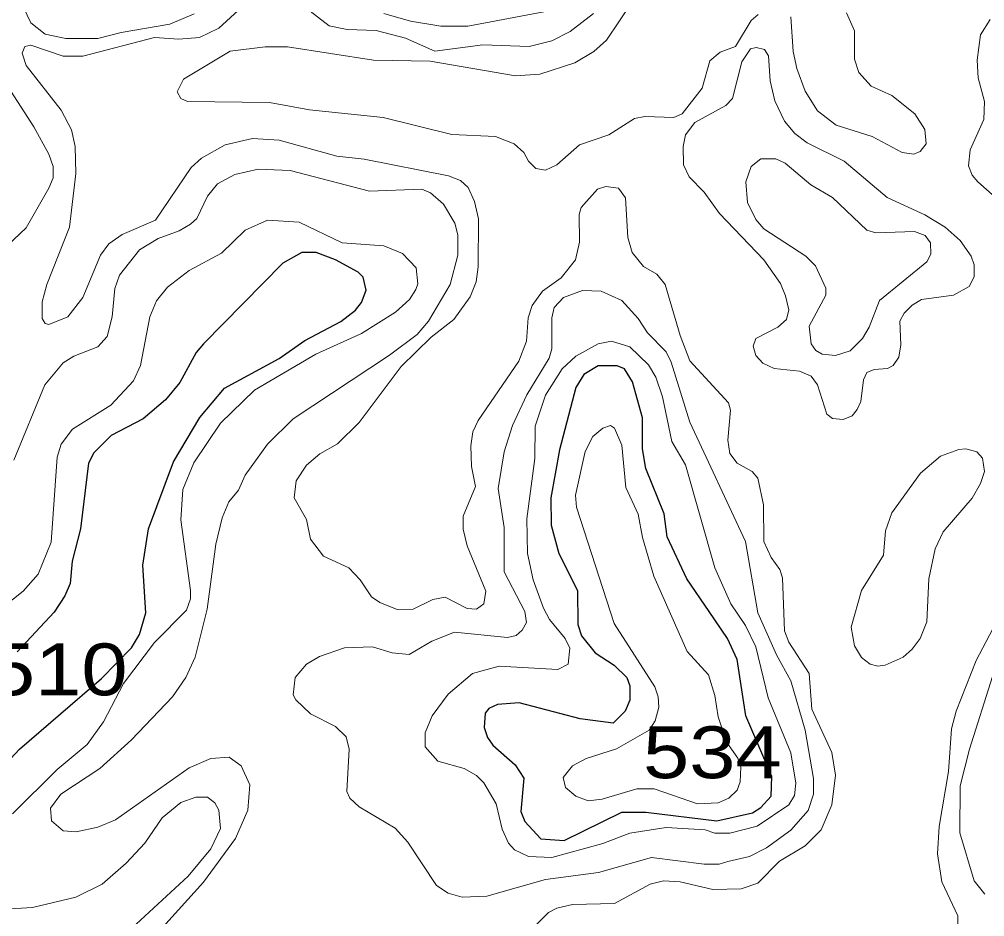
# Model space of a CAD drawing. Extents: x 577 to 602.9, y 7483.8 to 7511.6.
# Drawn here: x 599.599 to 601.089, y 7486.922 to 7488.307 of the extents above; entities that cross this region are included whole.
import ezdxf
from ezdxf.enums import TextEntityAlignment as Align

# ---------------------------------------------------------------- set-up
doc = ezdxf.new("R2010")
doc.units = 0
doc.header["$LTSCALE"] = 0.032
doc.layers.add('1', color=7, linetype='Continuous', lineweight=25)
doc.layers.add('2', color=7, linetype='Continuous', lineweight=13)
doc.layers.add('61', color=7, linetype='Continuous')

msp = doc.modelspace()

# ---------------------------------------------------------------- linework, layer by layer
at = {"layer": '1'}
msp.add_lwpolyline([(599.5786, 7487.1589), (599.5992, 7487.1808), (599.7257, 7487.29), (599.7717, 7487.3374), (599.7844, 7487.3581), (599.794, 7487.3915), (599.7892, 7487.4646), (599.798, 7487.5211), (599.8369, 7487.6244), (599.8775, 7487.6928), (599.9156, 7487.7382), (599.9999, 7487.7835), (600.0397, 7487.8113), (600.0953, 7487.8407), (600.1176, 7487.8582), (600.1272, 7487.8702), (600.1343, 7487.8892), (600.1295, 7487.9091), (600.1216, 7487.9171), (600.0866, 7487.9362), (600.0572, 7487.9473), (600.0349, 7487.9473), (600.0055, 7487.9306), (599.883, 7487.8065), (599.8719, 7487.793), (599.8465, 7487.7469), (599.8242, 7487.7199), (599.79, 7487.6904), (599.7407, 7487.665), (599.7137, 7487.638), (599.7057, 7487.6221), (599.693, 7487.5211), (599.6803, 7487.471), (599.6771, 7487.4368), (599.6691, 7487.4177), (599.6524, 7487.3923), (599.5952, 7487.331)], dxfattribs=at)
msp.add_lwpolyline([(600.6636, 7487.3934), (600.6289, 7487.4439), (600.5987, 7487.5084), (600.5939, 7487.5441), (600.5661, 7487.6141), (600.5605, 7487.6443), (600.5605, 7487.692), (600.5454, 7487.7477), (600.5327, 7487.7676), (600.5216, 7487.7724), (600.4921, 7487.7724), (600.4699, 7487.7588), (600.4579, 7487.739), (600.4325, 7487.6427), (600.419, 7487.5688), (600.4198, 7487.5266), (600.4317, 7487.4829), (600.4603, 7487.4257), (600.4611, 7487.3732), (600.4667, 7487.3557), (600.4874, 7487.3294), (600.5168, 7487.3104), (600.5367, 7487.2913), (600.5414, 7487.2785), (600.5409, 7487.2566), (600.534, 7487.2394), (600.5156, 7487.221), (600.4643, 7487.2277), (600.3705, 7487.2523), (600.3371, 7487.2499), (600.3236, 7487.2436), (600.318, 7487.2364), (600.3164, 7487.2141), (600.3212, 7487.199), (600.3299, 7487.1871), (600.3641, 7487.1569), (600.3776, 7487.1362), (600.3729, 7487.0845), (600.3792, 7487.0694), (600.4039, 7487.0424), (600.4397, 7487.04), (600.5287, 7487.0837), (600.5661, 7487.0837), (600.6753, 7487.0704), (600.7307, 7487.0829), (600.7434, 7487.0909), (600.7593, 7487.1084), (600.7601, 7487.1386), (600.7204, 7487.2324), (600.7068, 7487.3191), (600.6917, 7487.3517)], close=True, dxfattribs=at)
at = {"layer": '2'}
for points in [[(599.5578, 7488.4236), (599.6167, 7488.3019), (599.6389, 7488.2844), (599.6707, 7488.2773), (599.72, 7488.2773), (599.7558, 7488.2868), (599.8313, 7488.2996), (599.8687, 7488.3155)], [(600.5454, 7488.3345), (600.5049, 7488.2749), (600.4858, 7488.2574), (600.4564, 7488.2399), (600.4023, 7488.2224), (600.3649, 7488.22), (600.2329, 7488.2423), (600.1454, 7488.2439), (600.0126, 7488.2646), (599.9785, 7488.2646), (599.9244, 7488.2582), (599.852, 7488.2145), (599.8425, 7488.1954), (599.848, 7488.185), (599.8584, 7488.1803), (599.9848, 7488.1787), (600.0468, 7488.1676), (600.1606, 7488.1556), (600.2663, 7488.1294), (600.3339, 7488.1262)], [(599.9546, 7488.3377), (599.9069, 7488.2932), (599.8767, 7488.2789), (599.8449, 7488.2765)], [(600.485, 7488.3163), (600.4492, 7488.2884), (600.4206, 7488.2741), (600.3856, 7488.2654), (600.314, 7488.2677), (600.2401, 7488.2582), (600.1947, 7488.2781), (600.1494, 7488.29), (600.1049, 7488.2916), (600.0771, 7488.2972), (600.023, 7488.3393)], [(600.1613, 7488.3163), (600.2027, 7488.3043), (600.2496, 7488.2964), (600.291, 7488.2964), (600.4086, 7488.3186)], [(600.7895, 7488.3107), (600.7935, 7488.2574), (600.7991, 7488.2312), (600.8118, 7488.1962), (600.8309, 7488.166), (600.8595, 7488.1437), (600.9152, 7488.1262), (600.9613, 7488.1016), (600.9796, 7488.0992), (600.9891, 7488.1031), (600.9987, 7488.1151), (600.9963, 7488.1373), (600.9812, 7488.1612), (600.9454, 7488.1898), (600.9136, 7488.2041), (600.8945, 7488.2248), (600.8881, 7488.2455), (600.8881, 7488.2892), (600.8754, 7488.317)], [(600.3339, 7488.1262), (600.3625, 7488.1151), (600.3776, 7488.1016), (600.3848, 7488.088), (600.3959, 7488.0769), (600.411, 7488.0745), (600.4285, 7488.0825), (600.4635, 7488.1135), (600.5088, 7488.1286), (600.5486, 7488.154), (600.5645, 7488.1572), (600.609, 7488.1556), (600.6218, 7488.1612), (600.6528, 7488.201), (600.6647, 7488.2431), (600.6806, 7488.2566), (600.7045, 7488.2654), (600.7283, 7488.3051), (600.7394, 7488.3147)], [(601.114, 7488.0252), (601.0782, 7488.0562), (601.0694, 7488.0666), (601.0639, 7488.0809), (601.0663, 7488.1055), (601.0877, 7488.1524), (601.0885, 7488.1803), (601.079, 7488.2169), (601.0774, 7488.2439), (601.0822, 7488.2829), (601.0973, 7488.3067)], [(599.8449, 7488.2765), (599.8075, 7488.2789), (599.697, 7488.2503), (599.6667, 7488.2503), (599.6167, 7488.267), (599.6071, 7488.2654), (599.6031, 7488.255), (599.6095, 7488.2359), (599.6636, 7488.1668), (599.6795, 7488.1365), (599.685, 7488.1111), (599.6858, 7488.069), (599.6763, 7487.9863), (599.6413, 7487.898), (599.6341, 7487.871), (599.6341, 7487.8455), (599.6389, 7487.8376), (599.6445, 7487.836), (599.6739, 7487.8479), (599.697, 7487.8781), (599.724, 7487.9433), (599.7367, 7487.9608), (599.7574, 7487.9751), (599.8091, 7487.9974), (599.864, 7488.0785), (599.8799, 7488.0928), (599.9164, 7488.1135), (599.9586, 7488.123), (599.9999, 7488.1206), (600.089, 7488.096), (600.1311, 7488.0912), (600.2615, 7488.0658), (600.2798, 7488.0586), (600.2918, 7488.0475), (600.3013, 7488.026), (600.3077, 7487.999), (600.3069, 7487.925), (600.3037, 7487.902), (600.2949, 7487.8789), (600.2695, 7487.8439), (600.2345, 7487.8169), (600.1884, 7487.7716), (600.1232, 7487.6849), (600.0898, 7487.6523), (600.0627, 7487.6364), (600.0421, 7487.6189), (600.0262, 7487.595), (600.023, 7487.5688), (600.0421, 7487.5354), (600.0484, 7487.5052), (600.0683, 7487.4789), (600.1073, 7487.4606), (600.1248, 7487.4424), (600.1423, 7487.4161), (600.155, 7487.4074), (600.182, 7487.3962), (600.2067, 7487.397), (600.2369, 7487.4121), (600.256, 7487.4153), (600.2902, 7487.3978), (600.3045, 7487.397), (600.3156, 7487.405), (600.3188, 7487.4249), (600.2902, 7487.4948), (600.2838, 7487.5203), (600.2838, 7487.5402), (600.3029, 7487.5863), (600.2965, 7487.6173), (600.2957, 7487.6491), (600.2989, 7487.6706), (600.3069, 7487.6881), (600.3697, 7487.7795), (600.3816, 7487.8105), (600.384, 7487.8463), (600.3904, 7487.8654), (600.4063, 7487.8877), (600.4349, 7487.9083), (600.4572, 7487.9362), (600.4635, 7487.9632), (600.4627, 7488.0061), (600.4659, 7488.0165), (600.4913, 7488.0451), (600.5041, 7488.0491), (600.5239, 7488.0467), (600.5343, 7488.0316), (600.5383, 7487.9704), (600.5446, 7487.9473), (600.5621, 7487.9258), (600.5828, 7487.9139), (600.5955, 7487.898), (600.6186, 7487.8193), (600.6337, 7487.7803), (600.6933, 7487.7151), (600.6965, 7487.704), (600.6925, 7487.6578), (600.6957, 7487.6372), (600.7068, 7487.6221), (600.7299, 7487.6093), (600.7386, 7487.599), (600.7474, 7487.5577), (600.7482, 7487.5012)], [(599.5514, 7487.9306), (599.6095, 7487.9855), (599.6445, 7488.0467), (599.6508, 7488.0626), (599.6508, 7488.0801), (599.6445, 7488.0992), (599.6214, 7488.1413), (599.5809, 7488.2033)], [(600.2536, 7488.022), (600.2337, 7488.0395), (600.2202, 7488.0451), (600.1391, 7488.0419), (600.0166, 7488.0737), (599.9673, 7488.0761), (599.9315, 7488.0674), (599.9045, 7488.053), (599.8894, 7488.034), (599.8727, 7487.9998), (599.8632, 7487.991), (599.8457, 7487.9807), (599.8131, 7487.9688), (599.7844, 7487.9513), (599.7534, 7487.9123), (599.7463, 7487.8916), (599.7423, 7487.8479), (599.7343, 7487.8177), (599.72, 7487.8018), (599.6827, 7487.7875), (599.6667, 7487.7771), (599.6381, 7487.7429), (599.5904, 7487.6268)], [(599.8202, 7486.9064), (599.883, 7486.9756), (599.9323, 7487.0432), (599.9514, 7487.0869), (599.9546, 7487.1259), (599.9411, 7487.1553), (599.9228, 7487.1688), (599.8942, 7487.1664), (599.8608, 7487.1521), (599.7471, 7487.0718), (599.72, 7487.0607), (599.6866, 7487.0535), (599.6667, 7487.0551), (599.6485, 7487.0702), (599.6469, 7487.0901), (599.6628, 7487.1116), (599.7232, 7487.1513), (599.7717, 7487.1951), (599.8353, 7487.2618), (599.856, 7487.2913), (599.8703, 7487.3231), (599.8886, 7487.397), (599.9021, 7487.4972), (599.9117, 7487.5378), (599.922, 7487.5624), (599.9371, 7487.5807), (599.9474, 7487.6038), (599.9816, 7487.6515), (600.0214, 7487.6904), (600.1701, 7487.7891), (600.213, 7487.8209), (600.2305, 7487.8415), (600.2639, 7487.898), (600.2759, 7487.9433), (600.2759, 7487.9743), (600.2711, 7487.9926), (600.2536, 7488.022)], [(599.5618, 7487.3915), (599.6047, 7487.4249), (599.6278, 7487.4511), (599.6477, 7487.5004), (599.6572, 7487.6316), (599.6636, 7487.6515), (599.6811, 7487.6745), (599.7399, 7487.7119), (599.7749, 7487.7493), (599.786, 7487.7731), (599.8003, 7487.8479), (599.8107, 7487.8725), (599.8274, 7487.894), (599.8608, 7487.9195), (599.9109, 7487.9465), (599.9474, 7487.9815), (599.9816, 7487.9974), (600.0309, 7487.9942), (600.0969, 7487.9624), (600.1613, 7487.9576), (600.19, 7487.9457), (600.2114, 7487.9234), (600.2138, 7487.8988), (600.2106, 7487.89), (600.2011, 7487.8749), (600.1796, 7487.8551), (600.1272, 7487.8224), (600.0564, 7487.7906), (599.9618, 7487.735), (599.9093, 7487.6841), (599.8679, 7487.6229), (599.8512, 7487.5815), (599.848, 7487.5346), (599.8632, 7487.4257), (599.8632, 7487.4129), (599.8568, 7487.3954), (599.8075, 7487.3453), (599.7598, 7487.2825), (599.7288, 7487.2229), (599.7033, 7487.1879), (599.6572, 7487.1497), (599.588, 7487.0813)], [(600.7482, 7487.5012), (600.7593, 7487.4765), (600.7728, 7487.4583), (600.7768, 7487.4455), (600.78, 7487.3636), (600.7864, 7487.3461), (600.8182, 7487.2976), (600.8221, 7487.2428), (600.8531, 7487.176), (600.8587, 7487.141), (600.8531, 7487.0949), (600.8365, 7487.0567), (600.8118, 7487.032), (600.772, 7487.0082), (600.7386, 7486.974), (600.7132, 7486.9652), (600.6695, 7486.9645), (600.6186, 7486.9764), (600.5931, 7486.978), (600.5725, 7486.9724), (600.5176, 7486.943), (600.4524, 7486.9414), (600.4285, 7486.9358), (600.4158, 7486.9287), (600.3601, 7486.8738)], [(601.0472, 7486.9112), (601.0472, 7486.9239), (601.0225, 7486.9764), (601.0162, 7487.0193), (601.0185, 7487.0615), (601.0329, 7487.1465), (601.0376, 7487.2125), (601.0448, 7487.2396), (601.0758, 7487.3175), (601.1116, 7487.3859)], [(601.1012, 7487.2929), (601.0655, 7487.1807), (601.0511, 7487.1243), (601.0504, 7487.0519), (601.0726, 7486.978), (601.0893, 7486.9573)], [(599.5674, 7486.9334), (599.619, 7486.9366), (599.6858, 7486.9525), (599.7264, 7486.9724), (599.7638, 7487.005), (599.7924, 7487.036), (599.8194, 7487.075), (599.848, 7487.0988), (599.8711, 7487.1068), (599.8894, 7487.1068), (599.9005, 7487.098), (599.9069, 7487.0869), (599.9093, 7487.0583), (599.8942, 7487.0273), (599.8592, 7486.9851), (599.7725, 7486.9048)]]:
    msp.add_lwpolyline(points, dxfattribs=at)
for points in [[(600.9597, 7487.805), (600.9565, 7487.7859), (600.9478, 7487.7731), (600.939, 7487.7684), (600.9184, 7487.7668), (600.9072, 7487.762), (600.9017, 7487.7509), (600.8977, 7487.7175), (600.8921, 7487.7048), (600.8842, 7487.6952), (600.8706, 7487.6897), (600.8539, 7487.6912), (600.8452, 7487.6976), (600.8309, 7487.7429), (600.8213, 7487.7564), (600.8031, 7487.7644), (600.7641, 7487.7684), (600.7466, 7487.7763), (600.7355, 7487.7883), (600.7315, 7487.8026), (600.7355, 7487.8145), (600.7697, 7487.832), (600.7832, 7487.8439), (600.7864, 7487.859), (600.7816, 7487.8805), (600.7736, 7487.8996), (600.7482, 7487.9362), (600.6798, 7488.0077), (600.6559, 7488.0403), (600.6329, 7488.0642), (600.6241, 7488.0825), (600.6233, 7488.1111), (600.6273, 7488.1286), (600.6416, 7488.1477), (600.6893, 7488.1739), (600.6997, 7488.185), (600.714, 7488.2415), (600.7275, 7488.2614), (600.7363, 7488.2638), (600.749, 7488.2606), (600.7553, 7488.251), (600.7577, 7488.2121), (600.7649, 7488.1811), (600.78, 7488.1501), (600.7959, 7488.131), (600.815, 7488.1167), (600.8722, 7488.088), (600.9382, 7488.0324), (600.9963, 7488.0053), (601.0281, 7487.9863), (601.0511, 7487.9656), (601.0678, 7487.9417), (601.0726, 7487.9282), (601.0726, 7487.9099), (601.0647, 7487.8948), (601.0408, 7487.8813), (600.9915, 7487.8749), (600.9772, 7487.8662), (600.9645, 7487.8535), (600.9581, 7487.8415)], [(600.9001, 7487.8145), (600.881, 7487.7954), (600.8587, 7487.7883), (600.838, 7487.7906), (600.8285, 7487.7962), (600.8213, 7487.8065), (600.8182, 7487.8336), (600.8436, 7487.8813), (600.8436, 7487.8924), (600.8277, 7487.9266), (600.8126, 7487.9417), (600.7482, 7487.9839), (600.7355, 7487.9982), (600.7227, 7488.0244), (600.7204, 7488.0562), (600.7283, 7488.0801), (600.7434, 7488.092), (600.7665, 7488.092), (600.7808, 7488.0849), (600.8205, 7488.0515), (600.8539, 7488.0324), (600.9072, 7487.9815), (600.9207, 7487.9775), (600.9804, 7487.9799), (600.9971, 7487.9735), (601.005, 7487.9624), (601.0058, 7487.9449), (600.9995, 7487.933), (600.9263, 7487.8733), (600.9104, 7487.832)], [(600.6925, 7487.0074), (600.7259, 7487.0153), (600.7522, 7487.0289), (600.7895, 7487.0559), (600.8166, 7487.0861), (600.8245, 7487.1116), (600.8245, 7487.1354), (600.8118, 7487.2102), (600.7895, 7487.2865), (600.7673, 7487.3263), (600.7386, 7487.3915), (600.7196, 7487.5012), (600.6337, 7487.6857), (600.6051, 7487.7779), (600.5971, 7487.7938), (600.5685, 7487.8232), (600.5542, 7487.8455), (600.5287, 7487.8733), (600.4969, 7487.8877), (600.4683, 7487.8884), (600.4389, 7487.8781), (600.4245, 7487.8622), (600.4206, 7487.8463), (600.4206, 7487.7986), (600.4166, 7487.7843), (600.3824, 7487.7278), (600.3601, 7487.6801), (600.3474, 7487.6396), (600.3379, 7487.5831), (600.3474, 7487.5227), (600.3474, 7487.4543), (600.3792, 7487.3931), (600.3816, 7487.3764), (600.3752, 7487.3644), (600.3657, 7487.3565), (600.3522, 7487.3533), (600.2703, 7487.3612), (600.2353, 7487.3477), (600.2003, 7487.3271), (600.1741, 7487.3294), (600.1439, 7487.339), (600.1009, 7487.3374), (600.0619, 7487.3239), (600.0421, 7487.3119), (600.0246, 7487.2913), (600.0214, 7487.265), (600.0254, 7487.2571), (600.0484, 7487.2356), (600.0866, 7487.2157), (600.1033, 7487.1998), (600.1081, 7487.1807), (600.1041, 7487.1155), (600.1089, 7487.1052), (600.1232, 7487.0917), (600.1788, 7487.0591), (600.1987, 7487.0376), (600.2425, 7486.9708), (600.2607, 7486.9589), (600.2822, 7486.9525), (600.3204, 7486.9541), (600.411, 7486.9796), (600.4929, 7486.9907), (600.5748, 7487.0138), (600.6559, 7487.0034), (600.679, 7487.0034)], [(600.5971, 7487.0599), (600.5414, 7487.0511), (600.4993, 7487.0352), (600.4206, 7487.0138), (600.3848, 7487.0153), (600.3633, 7487.0257), (600.3538, 7487.036), (600.3442, 7487.0575), (600.3347, 7487.0965), (600.3156, 7487.1291), (600.3045, 7487.1402), (600.2854, 7487.1513), (600.2448, 7487.1625), (600.225, 7487.1847), (600.225, 7487.2062), (600.2361, 7487.2324), (600.2607, 7487.2658), (600.2981, 7487.2976), (600.3395, 7487.3088), (600.4301, 7487.304), (600.446, 7487.3119), (600.4484, 7487.3366), (600.4412, 7487.3517), (600.4174, 7487.3811), (600.4079, 7487.3986), (600.3919, 7487.4424), (600.3832, 7487.4829), (600.3824, 7487.5362), (600.3943, 7487.6292), (600.3951, 7487.6793), (600.411, 7487.727), (600.4365, 7487.7676), (600.4579, 7487.7875), (600.4921, 7487.8065), (600.5128, 7487.8105), (600.5414, 7487.8018), (600.5701, 7487.7739), (600.5812, 7487.7549), (600.5915, 7487.7246), (600.6059, 7487.6555), (600.6273, 7487.6197), (600.6726, 7487.4606), (600.6973, 7487.405), (600.7196, 7487.3716), (600.7355, 7487.339), (600.7545, 7487.2603), (600.7895, 7487.1752), (600.7975, 7487.1283), (600.7951, 7487.1092), (600.7864, 7487.0949), (600.7378, 7487.0623), (600.6957, 7487.0511), (600.6726, 7487.0511), (600.6572, 7487.0563)], [(600.6626, 7487.2955), (600.6725, 7487.2637), (600.6774, 7487.2308), (600.6909, 7487.1911), (600.7076, 7487.1672), (600.7124, 7487.1529), (600.7116, 7487.1306), (600.7068, 7487.1179), (600.6941, 7487.1052), (600.6774, 7487.098), (600.6456, 7487.0965), (600.5788, 7487.1195), (600.5518, 7487.1195), (600.4985, 7487.1036), (600.477, 7487.1012), (600.4579, 7487.1084), (600.442, 7487.1219), (600.4381, 7487.137), (600.4524, 7487.1553), (600.4739, 7487.1664), (600.5208, 7487.1815), (600.5709, 7487.2102), (600.5804, 7487.2247), (600.5858, 7487.2456), (600.5849, 7487.2618), (600.5797, 7487.2772), (600.5168, 7487.3748), (600.4587, 7487.5545), (600.4572, 7487.5728), (600.4723, 7487.6404), (600.4842, 7487.6634), (600.4993, 7487.6761), (600.5112, 7487.6801), (600.5176, 7487.6761), (600.5287, 7487.6499), (600.5351, 7487.5847), (600.5542, 7487.5433), (600.5605, 7487.5076), (600.578, 7487.4479), (600.6297, 7487.3318)], [(601.0853, 7487.63), (601.0885, 7487.6093), (601.0822, 7487.5911), (601.0694, 7487.568), (601.0249, 7487.5163), (601.0122, 7487.4901), (601.0026, 7487.4439), (600.9995, 7487.3772), (600.9891, 7487.3517), (600.9772, 7487.335), (600.9629, 7487.3231), (600.9351, 7487.3104), (600.9239, 7487.3088), (600.912, 7487.3119), (600.8985, 7487.3223), (600.8881, 7487.3406), (600.8826, 7487.3692), (600.8985, 7487.4257), (600.9327, 7487.4805), (600.9358, 7487.5179), (600.9454, 7487.5457), (600.9899, 7487.607), (601.0209, 7487.6332), (601.0488, 7487.6435), (601.0599, 7487.6443), (601.0766, 7487.6396)]]:
    msp.add_lwpolyline(points, close=True, dxfattribs=at)

# ---------------------------------------------------------------- texts
at = {"layer": '61', "width": 1.2}
for s, p in [('510', (599.6588, 7487.264)), ('534', (600.6685, 7487.1361))]:
    msp.add_text(s, height=0.08, dxfattribs=at).set_placement(p, align=Align.CENTER)

doc.saveas('drawing.dxf')
